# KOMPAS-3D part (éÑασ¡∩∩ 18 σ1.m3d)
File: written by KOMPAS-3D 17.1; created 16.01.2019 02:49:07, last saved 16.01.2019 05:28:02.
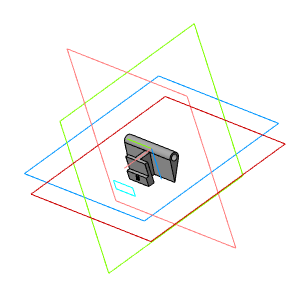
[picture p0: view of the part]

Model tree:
1. Эскиз:1
2. Элемент выдавливания:1
     Расстояние 1 = 9.5; Расстояние 2 = 9.5
3. Смещенная плоскость:1
     Расстояние = 6.76
4. Эскиз:2
5. Элемент выдавливания:2
     Расстояние 1 = 6.76
6. Эскиз:3
7. Элемент выдавливания:3
     Расстояние 1 = 3
8. Эскиз:4
9. Элемент выдавливания:4
     Расстояние 2 = 4
10. Смещенная плоскость:2
     Расстояние = 5
11. Эскиз:5
12. Элемент выдавливания:5
     Расстояние 2 = 6; Смещение 2 = 1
